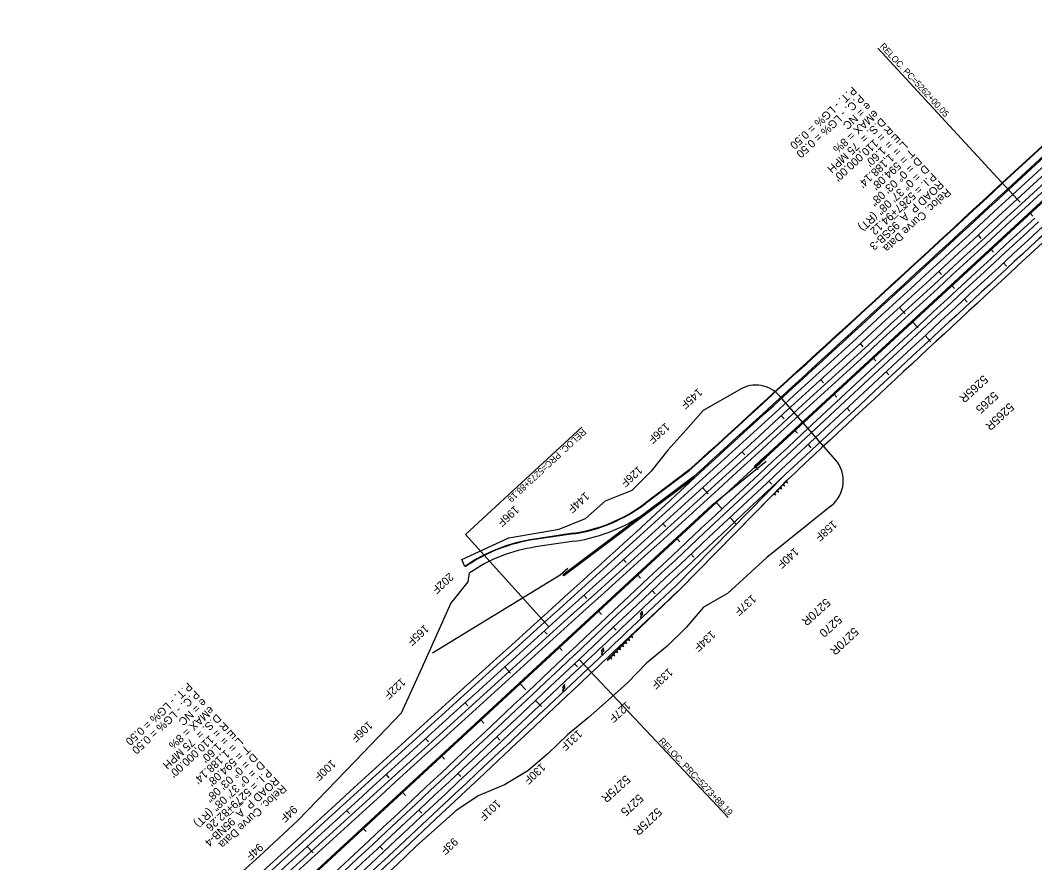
# Model space of a CAD drawing. Extents: x 2160876 to 2175625, y 601634 to 617693.
# Drawn here: x 2163705 to 2165605, y 606388 to 607966 of the extents above; entities that cross this region are included whole.
import ezdxf

# ---------------------------------------------------------------- set-up
doc = ezdxf.new("R2010")
doc.units = 0
for name, color, linetype in [('Level 20', 7, 'Continuous'), ('RD_HC_Cl', 7, 'Continuous'), ('RD_HC_CL_Rel', 7, 'Continuous'), ('RD_HC_Data_Rel', 7, 'Continuous'), ('RD_HC_Data_Tic', 7, 'Continuous'), ('RD_HC_Data_Tic_Rel', 7, 'Continuous'), ('RD_HC_TX_Rel_Sta50', 7, 'Continuous'), ('RD_HC_TX_Sta50', 7, 'Continuous'), ('RD_PD_CstnLmt', 7, 'Continuous'), ('RD_PD_Fence', 7, 'Continuous'), ('RD_PD_Final_LnLine', 7, 'Continuous'), ('RD_PD_Final_TrvlWay', 7, 'Continuous'), ('RD_PD_GR', 7, 'Continuous'), ('RD_PD_MedBWall', 7, 'Continuous'), ('RD_PD_MedGR', 7, 'Continuous')]:
    doc.layers.add(name, color=color, linetype=linetype)

msp = doc.modelspace()

# ---------------------------------------------------------------- linework, layer by layer
at = {"layer": 'Level 20'}
for points in [[(2164870.1, 606859), (2164866.1, 606853.3), (2164867.7, 606853.1)], [(2164867.7, 606853.1), (2164868, 606853.1), (2164866.4, 606847), (2164866.9, 606846.9)], [(2164866.9, 606846.9), (2164867.4, 606846.8), (2164869, 606852.8), (2164870.8, 606852), (2164870.1, 606859)], [(2164797.4, 606790.4), (2164793.3, 606784.7), (2164794.9, 606784.5)], [(2164794.9, 606784.5), (2164795.2, 606784.5), (2164793.6, 606778.4), (2164794.1, 606778.3)], [(2164794.1, 606778.3), (2164794.7, 606778.2), (2164796.3, 606784.2), (2164798, 606783.4), (2164797.4, 606790.4)], [(2164724.6, 606721.8), (2164720.6, 606716.1), (2164722.2, 606715.9)], [(2164722.2, 606715.9), (2164722.5, 606715.9), (2164720.8, 606709.8), (2164721.4, 606709.7)], [(2164721.4, 606709.7), (2164721.9, 606709.6), (2164723.5, 606715.6), (2164725.2, 606714.8), (2164724.6, 606721.8)]]:
    msp.add_lwpolyline(points, dxfattribs=at)
at = {"layer": 'RD_HC_Cl'}
msp.add_line((2172239.9, 613739.9), (2163704.8, 605858.6), dxfattribs=at)
at = {"layer": 'RD_HC_CL_Rel'}
msp.add_line((2168658.1, 610480.3), (2165572.4, 607631), dxfattribs=at)
for centre, start, end in [((2090947.4, 688446.2), 312.100607, 312.719474), ((2240245.2, 526764.1), 132.719474, 133.338341), ((2238443, 525213.1), 132.100607, 132.719474), ((2089258, 686773.1), 312.719474, 313.338341)]:
    msp.add_arc(centre, 110000, start, end, dxfattribs=at)
at = {"layer": 'RD_HC_Data_Rel'}
for p, q in [((2165572.4, 607631), (2165311.5, 607913.6)), ((2164538.9, 607002.7), (2164756.5, 607203.6)), ((2164695.2, 606829.7), (2164538.9, 607002.7)), ((2164751.6, 606768.6), (2165031.1, 606472.4))]:
    msp.add_line(p, q, dxfattribs=at)
at = {"layer": 'RD_HC_Data_Tic'}
for p, q in [((2165596.3, 607605.2), (2165601.7, 607599.3)), ((2165522.8, 607537.3), (2165528.2, 607531.4)), ((2165449.3, 607469.5), (2165454.8, 607463.6)), ((2165375.9, 607401.6), (2165386.7, 607389.9)), ((2165302.4, 607333.8), (2165307.8, 607327.9)), ((2165228.9, 607266), (2165234.4, 607260.1)), ((2165155.5, 607198.1), (2165160.9, 607192.2)), ((2165082, 607130.3), (2165087.4, 607124.4)), ((2165008.5, 607062.4), (2165019.4, 607050.7)), ((2164935.1, 606994.6), (2164940.5, 606988.7)), ((2164861.6, 606926.7), (2164867, 606920.9)), ((2164788.1, 606858.9), (2164793.6, 606853)), ((2164714.7, 606791.1), (2164720.1, 606785.2)), ((2164641.2, 606723.2), (2164652.1, 606711.5)), ((2164567.7, 606655.4), (2164573.2, 606649.5)), ((2164494.3, 606587.5), (2164499.7, 606581.7)), ((2164420.8, 606519.7), (2164426.2, 606513.8)), ((2164347.3, 606451.9), (2164352.8, 606446))]:
    msp.add_line(p, q, dxfattribs=at)
at = {"layer": 'RD_HC_Data_Tic_Rel'}
for p, q in [((2165572.5, 607631), (2165577.9, 607625.1)), ((2165499, 607563.2), (2165504.4, 607557.3)), ((2165546.7, 607511.5), (2165552.2, 607505.6)), ((2165425.4, 607495.5), (2165430.8, 607489.6)), ((2165473.4, 607443.5), (2165478.8, 607437.7)), ((2165351.8, 607427.8), (2165362.6, 607416)), ((2165400.1, 607375.5), (2165410.9, 607363.8)), ((2165278.1, 607360.2), (2165283.5, 607354.3)), ((2165326.8, 607307.5), (2165332.2, 607301.6)), ((2165204.4, 607292.7), (2165209.8, 607286.8)), ((2165130.5, 607225.2), (2165135.9, 607219.3)), ((2165253.6, 607239.3), (2165259.1, 607233.5)), ((2165180.5, 607171.1), (2165185.9, 607165.3)), ((2165056.7, 607157.8), (2165062.1, 607151.9)), ((2164982.7, 607090.4), (2164993.5, 607078.6)), ((2165107.4, 607102.8), (2165112.9, 607097)), ((2165034.4, 607034.5), (2165045.3, 607022.8)), ((2164908.8, 607023.2), (2164914.1, 607017.2)), ((2164834.7, 606956), (2164840.1, 606950)), ((2164961.5, 606966.1), (2164966.9, 606960.3)), ((2164888.6, 606897.6), (2164894.1, 606891.8)), ((2164760.6, 606888.8), (2164766, 606882.9)), ((2164686.4, 606821.8), (2164691.8, 606815.8)), ((2164815.8, 606829.1), (2164821.3, 606823.3)), ((2164612.3, 606754.7), (2164623, 606742.8)), ((2164743, 606760.5), (2164748.5, 606754.6)), ((2164670.2, 606691.9), (2164681.2, 606680.2)), ((2164538.2, 606687.5), (2164543.5, 606681.6)), ((2164464.1, 606620.3), (2164469.5, 606614.4)), ((2164597.4, 606623.4), (2164602.9, 606617.5)), ((2164390.2, 606553), (2164395.5, 606547.1)), ((2164524.5, 606554.9), (2164530, 606549.1)), ((2164316.2, 606485.7), (2164321.6, 606479.7)), ((2164451.6, 606486.5), (2164457, 606480.7)), ((2164242.4, 606418.2), (2164253.2, 606406.4)), ((2164378.5, 606418.2), (2164384, 606412.3))]:
    msp.add_line(p, q, dxfattribs=at)
at = {"layer": 'RD_PD_CstnLmt'}
for p, q in [((2164984.7, 607235.6), (2165052.8, 607274.5)), ((2165231.8, 607142.8), (2165127.7, 607261.9)), ((2164984.7, 607235.6), (2164951.5, 607197.9)), ((2164951.5, 607197.9), (2164918.1, 607160.4)), ((2164918.1, 607160.4), (2164886.4, 607121)), ((2165224.2, 607056.6), (2165103.5, 606959.6)), ((2165103.5, 606959.6), (2165029.4, 606892.4)), ((2165029.4, 606892.4), (2164985, 606866.8)), ((2164916.7, 606793.4), (2164878.1, 606761.5)), ((2164225.6, 606467.6), (2164152.6, 606399.2)), ((2164152.6, 606399.2), (2164077.9, 606332.8))]:
    msp.add_line(p, q, dxfattribs=at)
for points in [[(2164537.9, 606942.9), (2164531.9, 606955.8), (2164619.9, 606996.5), (2164714.3, 607012.5), (2164763.8, 607032.7), (2164801.3, 607065.7), (2164851.1, 607085.6), (2164886.4, 607121)], [(2164225.6, 606467.6), (2164332.1, 606578.3), (2164419, 606668.6), (2164457.4, 606753.8), (2164511.4, 606873.3), (2164543.9, 606914.3), (2164546.6, 606930.7)], [(2164985, 606866.8), (2164952.2, 606828.7), (2164916.7, 606793.4)], [(2164878.1, 606761.5), (2164843.2, 606725.6), (2164806, 606692.2), (2164768.4, 606659.1), (2164729.9, 606627.2), (2164693.8, 606592.6), (2164655.6, 606560.2), (2164612.2, 606533.5), (2164562.8, 606513.4), (2164521, 606484.9), (2164446.2, 606418.5), (2164410.1, 606383.9), (2164335.8, 606317), (2164259.9, 606251.7), (2164185.8, 606184.6), (2164112.5, 606116.5), (2164041.3, 606046.2), (2163998.3, 605983.1)]]:
    msp.add_lwpolyline(points, dxfattribs=at)
for centre, start, end in [((2165082.5, 607222.4), 41.1644, 119.7089), ((2165186.6, 607103.3), 308.7929, 41.1644)]:
    msp.add_arc(centre, 60, start, end, dxfattribs=at)
at = {"layer": 'RD_PD_Fence'}
msp.add_lwpolyline([(2164730.7, 606938.9), (2164716.2, 606926.5), (2164476.9, 606780.3)], dxfattribs=at)
at = {"layer": 'RD_PD_Final_LnLine'}
for p, q in [((2168630.1, 610510.7), (2165544.4, 607661.4)), ((2168630.7, 610509.9), (2165545.1, 607660.6)), ((2168650, 610489.1), (2165564.3, 607639.8)), ((2168658.1, 610480.3), (2165572.4, 607631)), ((2168666.2, 610471.5), (2165580.6, 607622.2)), ((2164957.1, 607123), (2164874.6, 607060.8)), ((2164957.8, 607122.2), (2164875.2, 607060)), ((2164932.9, 606906.3), (2165138.6, 607115.5)), ((2164740.7, 607004.9), (2164667.9, 606994.2)), ((2164740.9, 607003.9), (2164668.1, 606993.2)), ((2164742.7, 606990), (2164670.1, 606979.3))]:
    msp.add_line(p, q, dxfattribs=at)
for centre, radius, start, end in [((2090947.4, 688446.2), 109958.7, 312.303996, 312.719474), ((2090947.4, 688446.2), 109959.7, 312.303996, 312.719474), ((2090947.4, 688446.2), 109988, 312.100607, 312.719474), ((2090947.4, 688446.2), 110000, 312.100607, 312.719474), ((2090947.4, 688446.2), 110012, 312.100607, 312.719474), ((2240245.2, 526764.1), 110012, 132.719474, 133.338341), ((2240245.2, 526764.1), 110000, 132.719474, 133.338341), ((2240245.2, 526764.1), 109988, 132.719474, 133.067682), ((2240245.2, 526764.1), 109988, 133.067682, 133.220424), ((2164698.2, 607294.8), 293, 278.2992, 306.927), ((2164698.2, 607294.8), 294, 278.2992, 307.0089), ((2164698.2, 607294.8), 308, 278.2992, 307.0089), ((2164712.5, 606690.4), 307, 98.3571, 124.66), ((2164712.5, 606690.4), 306, 98.3571, 124.66), ((2164712.5, 606690.4), 292, 98.3571, 124.6285), ((2240245.2, 526764.1), 109988, 133.220424, 133.338341), ((2240245.2, 526764.1), 109976, 133.220424, 133.338341), ((2238443, 525213.1), 110012, 132.100607, 132.719474), ((2238443, 525213.1), 110000, 132.100607, 132.719474), ((2238443, 525213.1), 109988, 132.100607, 132.719474), ((2089258, 686773.1), 109988, 312.719474, 313.338341), ((2089258, 686773.1), 110000, 312.719474, 313.338341), ((2089258, 686773.1), 110012, 312.802799, 313.338341), ((2089258, 686773.1), 110024, 312.863734, 313.338341)]:
    msp.add_arc(centre, radius, start, end, dxfattribs=at)
at = {"layer": 'RD_PD_Final_TrvlWay'}
for p, q in [((2168641.8, 610497.9), (2165556.1, 607648.6)), ((2168673, 610464.1), (2165587.4, 607614.8)), ((2164968.2, 607109.7), (2164858.6, 607007.3)), ((2164939.7, 606899), (2165145.5, 607108.4))]:
    msp.add_line(p, q, dxfattribs=at)
for centre, radius, start, end in [((2090947.4, 688446.2), 109976, 312.30394, 312.719474), ((2090947.4, 688446.2), 110022, 312.100607, 312.719474), ((2240245.2, 526764.1), 110022, 132.719474, 133.338341), ((2240245.2, 526764.1), 109978, 132.719474, 133.067545), ((2090947.4, 688446.2), 109978, 312.100607, 312.2258), ((2240245.2, 526764.1), 109966, 133.220424, 133.338341), ((2238443, 525213.1), 110022, 132.100607, 132.719474), ((2238443, 525213.1), 109978, 132.100607, 132.719474), ((2089258, 686773.1), 109978, 312.719474, 313.338341), ((2089258, 686773.1), 110034, 312.803121, 313.338341)]:
    msp.add_arc(centre, radius, start, end, dxfattribs=at)
at = {"layer": 'RD_PD_GR'}
for p, q in [((2165000.3, 607057.6), (2165102, 607140.1)), ((2165141.1, 607104.2), (2165115.3, 607077.6)), ((2165115.7, 607077.3), (2165141.4, 607103.8)), ((2165127.9, 607089.8), (2165129.1, 607091.1)), ((2165129.3, 607088.4), (2165127.9, 607089.8)), ((2165129.1, 607091.1), (2165130.5, 607089.7)), ((2165130.5, 607089.7), (2165129.3, 607088.4)), ((2165129.9, 607089.1), (2165130.8, 607088.2)), ((2165130.2, 607087.6), (2165131.4, 607088.8)), ((2165133.4, 607095.6), (2165134.6, 607096.8)), ((2165134.9, 607094.2), (2165133.4, 607095.6)), ((2165134.6, 607096.8), (2165136.1, 607095.4)), ((2165136.1, 607095.4), (2165134.9, 607094.2)), ((2165135.5, 607094.8), (2165136.4, 607093.9)), ((2165135.8, 607093.3), (2165137, 607094.6)), ((2165139, 607101.3), (2165140.2, 607102.6)), ((2165140.4, 607099.9), (2165139, 607101.3)), ((2165140.2, 607102.6), (2165141.6, 607101.2)), ((2165141.6, 607101.2), (2165140.4, 607099.9)), ((2165141, 607100.6), (2165141.9, 607099.7)), ((2165141.4, 607103.8), (2165141.1, 607104.2)), ((2165141.3, 607099.1), (2165142.5, 607100.3)), ((2165115.3, 607077.6), (2165115.7, 607077.3)), ((2165116.7, 607078.4), (2165117.9, 607079.6)), ((2165118.1, 607077), (2165116.7, 607078.4)), ((2165117.9, 607079.6), (2165119.4, 607078.2)), ((2165119.4, 607078.2), (2165118.1, 607077)), ((2165118.8, 607077.6), (2165119.7, 607076.7)), ((2165119, 607076.1), (2165120.3, 607077.3)), ((2165120.1, 607081.9), (2165119.7, 607082.2)), ((2165122.3, 607084.1), (2165123.5, 607085.3)), ((2165123.7, 607082.7), (2165122.3, 607084.1)), ((2165123.5, 607085.3), (2165124.9, 607084)), ((2165124.9, 607084), (2165123.7, 607082.7)), ((2165124.3, 607083.3), (2165125.2, 607082.5)), ((2165124.6, 607081.8), (2165125.8, 607083.1)), ((2165000.3, 607057.6), (2163734.9, 605889.1)), ((2164849.7, 606813.1), (2164806.1, 606769)), ((2164807.1, 606769.3), (2164850, 606812.7)), ((2164843.2, 606805.8), (2164844.4, 606807)), ((2164844.6, 606804.4), (2164843.2, 606805.8)), ((2164844.4, 606807), (2164845.8, 606805.6)), ((2164845.8, 606805.6), (2164844.6, 606804.4)), ((2164845.2, 606805), (2164846.1, 606804.1)), ((2164845.5, 606803.5), (2164846.7, 606804.7)), ((2164848.8, 606811.5), (2164850, 606812.7)), ((2164850.2, 606810.1), (2164848.8, 606811.5)), ((2164850, 606812.7), (2164849.7, 606813.1)), ((2164850, 606812.7), (2164851.4, 606811.3)), ((2164851.4, 606811.3), (2164850.2, 606810.1)), ((2164850.8, 606810.7), (2164851.7, 606809.8)), ((2164851.1, 606809.2), (2164852.3, 606810.4)), ((2164815.4, 606783.7), (2164818, 606781)), ((2164820.7, 606783), (2164821.9, 606784.3)), ((2164821.9, 606784.3), (2164823.3, 606782.8)), ((2164826.3, 606788.7), (2164827.5, 606789.9)), ((2164827.7, 606787.3), (2164826.3, 606788.7)), ((2164827.5, 606789.9), (2164828.9, 606788.5)), ((2164828.9, 606788.5), (2164827.7, 606787.3)), ((2164828.3, 606787.9), (2164829.2, 606787)), ((2164828.6, 606786.4), (2164829.8, 606787.7)), ((2164831.9, 606794.4), (2164833.1, 606795.6)), ((2164833.3, 606793), (2164831.9, 606794.4)), ((2164833.1, 606795.6), (2164834.6, 606794.2)), ((2164834.6, 606794.2), (2164833.3, 606793)), ((2164834, 606793.6), (2164834.8, 606792.7)), ((2164834.2, 606792.1), (2164835.5, 606793.4)), ((2164837.5, 606800.1), (2164838.8, 606801.3)), ((2164839, 606798.7), (2164837.5, 606800.1)), ((2164838.8, 606801.3), (2164840.2, 606799.9)), ((2164840.2, 606799.9), (2164839, 606798.7)), ((2164839.6, 606799.3), (2164840.5, 606798.4)), ((2164839.8, 606797.8), (2164841.1, 606799)), ((2164806.1, 606769), (2164806.8, 606768.2)), ((2164806.6, 606769.1), (2164806.9, 606768.7)), ((2164806.8, 606768.2), (2164807.5, 606769)), ((2164807.5, 606769), (2164807.1, 606769.3)), ((2164809.4, 606771.6), (2164810.7, 606772.9)), ((2164810.9, 606770.2), (2164809.4, 606771.6)), ((2164810.7, 606772.9), (2164812.1, 606771.5)), ((2164812.1, 606771.5), (2164810.9, 606770.2)), ((2164811.5, 606770.8), (2164812.4, 606770)), ((2164811.7, 606769.3), (2164813, 606770.6)), ((2164815, 606777.3), (2164816.3, 606778.6)), ((2164816.5, 606775.9), (2164815, 606777.3)), ((2164816.3, 606778.6), (2164817.7, 606777.2)), ((2164817.7, 606777.2), (2164816.5, 606775.9)), ((2164817.1, 606776.5), (2164818, 606775.7)), ((2164817.4, 606775), (2164818.6, 606776.3)), ((2164822.1, 606781.6), (2164820.7, 606783)), ((2164823.3, 606782.8), (2164822.1, 606781.6)), ((2164822.7, 606782.2), (2164823.6, 606781.3)), ((2164823, 606780.7), (2164824.2, 606782))]:
    msp.add_line(p, q, dxfattribs=at)
for points in [[(2165115.3, 607077.6), (2164939.7, 606899), (2164849.6, 606813.1)], [(2164806.9, 606768.7), (2164806.4, 606766.8), (2164804.7, 606768.6), (2164806.6, 606769.1)]]:
    msp.add_lwpolyline(points, dxfattribs=at)
at = {"layer": 'RD_PD_MedBWall'}
for p, q in [((2168640.2, 610499.7), (2165554.6, 607650.3)), ((2168641.8, 610497.9), (2165556.1, 607648.6)), ((2168454, 610245.6), (2165100.2, 607148.7)), ((2168455.6, 610243.9), (2165101.8, 607146.9)), ((2165101.8, 607146.9), (2165100.2, 607148.7)), ((2164966.7, 607111.5), (2164721.8, 606926.8)), ((2164968.2, 607109.7), (2164723.2, 606925)), ((2164723.2, 606925), (2164721.8, 606926.8))]:
    msp.add_line(p, q, dxfattribs=at)
for radius, start in [(109973.7, 312.303996), (109976, 312.30394)]:
    msp.add_arc((2090947.4, 688446.2), radius, start, 312.719474, dxfattribs=at)
at = {"layer": 'RD_PD_MedGR'}
for p, q in [((2165099.9, 607149), (2165080, 607130.7)), ((2165099.9, 607149), (2165080, 607130.7)), ((2165097.3, 607145.9), (2165080.4, 607130.3)), ((2165102.1, 607146.6), (2165082.3, 607128.3)), ((2165082.3, 607128.3), (2165102.1, 607146.6)), ((2165095.5, 607144.3), (2165095.8, 607144.6)), ((2165095.8, 607144.6), (2165097.3, 607145.9)), ((2165097.4, 607142.9), (2165095.8, 607144.6)), ((2165100.2, 607148.7), (2165097.3, 607145.9)), ((2165097.3, 607145.9), (2165100.2, 607148.7)), ((2165098.8, 607144.2), (2165097.3, 607145.9)), ((2165101.8, 607146.9), (2165098.8, 607144.2)), ((2165101.8, 607146.9), (2165098.8, 607144.2)), ((2165099.9, 607149), (2165100.2, 607148.7)), ((2165100.2, 607148.7), (2165099.9, 607149)), ((2165102.1, 607146.6), (2165101.8, 607146.9)), ((2165102.1, 607146.6), (2165101.8, 607146.9)), ((2165082.3, 607128.3), (2165080, 607130.7)), ((2165080.3, 607130.4), (2165080, 607130.7)), ((2165098.8, 607144.2), (2165081.9, 607128.6)), ((2165082.3, 607128.3), (2165082, 607128.6)), ((2165083.9, 607130.4), (2165082.3, 607132.1)), ((2165082.6, 607132.4), (2165084.5, 607134.1)), ((2165084.1, 607130.7), (2165082.6, 607132.4)), ((2165084.5, 607134.1), (2165084.8, 607134.4)), ((2165086.1, 607132.4), (2165084.5, 607134.1)), ((2165084.8, 607134.4), (2165086.7, 607136.2)), ((2165086.4, 607132.7), (2165084.8, 607134.4)), ((2165086.7, 607136.2), (2165087, 607136.4)), ((2165088.3, 607134.5), (2165086.7, 607136.2)), ((2165087, 607136.4), (2165088.9, 607138.2)), ((2165088.6, 607134.7), (2165087, 607136.4)), ((2165088.9, 607138.2), (2165089.2, 607138.5)), ((2165090.5, 607136.5), (2165088.9, 607138.2)), ((2165089.2, 607138.5), (2165091.1, 607140.2)), ((2165090.8, 607136.8), (2165089.2, 607138.5)), ((2165091.1, 607140.2), (2165091.4, 607140.5)), ((2165092.7, 607138.5), (2165091.1, 607140.2)), ((2165091.4, 607140.5), (2165093.3, 607142.3)), ((2165093, 607138.8), (2165091.4, 607140.5)), ((2165093.3, 607142.3), (2165093.6, 607142.5)), ((2165094.9, 607140.6), (2165093.3, 607142.3)), ((2165093.6, 607142.5), (2165095.5, 607144.3)), ((2165095.2, 607140.8), (2165093.6, 607142.5)), ((2165097.1, 607142.6), (2165095.5, 607144.3))]:
    msp.add_line(p, q, dxfattribs=at)
for points in [[(2165080, 607130.7), (2165080.3, 607130.4), (2165080.4, 607130.3)], [(2165080.4, 607130.3), (2165082.3, 607132.1), (2165082.6, 607132.4)], [(2165098.8, 607144.2), (2165097.4, 607142.9), (2165097.1, 607142.6), (2165095.2, 607140.8), (2165094.9, 607140.6), (2165093, 607138.8), (2165092.7, 607138.5), (2165090.8, 607136.8), (2165090.5, 607136.5), (2165088.6, 607134.7), (2165088.3, 607134.5), (2165086.4, 607132.7), (2165086.1, 607132.4), (2165084.1, 607130.7), (2165083.9, 607130.4), (2165081.9, 607128.6)], [(2165081.9, 607128.6), (2165082, 607128.6), (2165082.3, 607128.3)]]:
    msp.add_lwpolyline(points, dxfattribs=at)
for radius in [1.67, 1.67, 1.27, 1.27]:
    msp.add_arc((2165081.2, 607129.5), radius, 132.7195, 312.7195, dxfattribs=at)

# ---------------------------------------------------------------- texts
at = {"layer": 'RD_HC_Data_Rel'}
for s, height, rotation, p in [('RELOC. PC=5262+00.05', 12, 312.7195, (2165314.2, 607916.6)), ('P.T. - LG% = 0.50', 15, 222.7195, (2165263.7, 607843.1)), ('P.C. - LG% = 0.50', 15, 222.7195, (2165277.3, 607828.4)), ('e = NC', 15, 222.7195, (2165290.8, 607813.7)), ('eMAX = 8%', 15, 222.7195, (2165304.4, 607799)), ('D.S. =  75 MPH', 15, 222.7195, (2165318, 607784.3)), ("R = 110,000.00'", 15, 222.7195, (2165331.5, 607769.6)), ("E = 1.60'", 15, 222.7195, (2165345.1, 607754.9)), ("L = 1,188.14'", 15, 222.7195, (2165358.7, 607740.3)), ("T = 594.08'", 15, 222.7195, (2165372.2, 607725.6)), ('D = 0° 03\' 08"', 15, 222.7195, (2165385.8, 607710.9)), ('    = 0° 37\' 08" (RT)', 15, 222.7195, (2165399.4, 607696.2)), ('P.I. = 5267+94.12', 15, 222.7195, (2165412.9, 607681.5)), ('D', 15, 222.7195, (2165399.4, 607696.2)), ('ROAD P_A_95SB-3', 15, 222.7195, (2165426.5, 607666.8)), ('Reloc. Curve Data', 15, 222.7195, (2165440.1, 607652.1)), ('RELOC. PRC=5273+88.19', 12, 222.7195, (2164758.3, 607201.7)), ('P.T. - LG% = 0.50', 15, 222.7195, (2164019, 606726.3)), ('P.C. - LG% = 0.50', 15, 222.7195, (2164032.5, 606711.6)), ('e = NC', 15, 222.7195, (2164046.1, 606696.9)), ('eMAX = 8%', 15, 222.7195, (2164059.7, 606682.2)), ('D.S. =  75 MPH', 15, 222.7195, (2164073.2, 606667.5)), ("R = 110,000.00'", 15, 222.7195, (2164086.8, 606652.8)), ("E = 1.60'", 15, 222.7195, (2164100.4, 606638.1)), ("L = 1,188.14'", 15, 222.7195, (2164113.9, 606623.4)), ('RELOC. PRC=5273+88.19', 12, 313.3383, (2164899.9, 606615.2)), ("T = 594.08'", 15, 222.7195, (2164127.5, 606608.7)), ('D = 0° 03\' 08"', 15, 222.7195, (2164141.1, 606594)), ('D', 15, 222.7195, (2164154.6, 606579.3)), ('    = 0° 37\' 08" (RT)', 15, 222.7195, (2164154.6, 606579.3)), ('P.I. = 5279+82.26', 15, 222.7195, (2164168.2, 606564.6)), ('ROAD P_A_95NB-4', 15, 222.7195, (2164181.8, 606550)), ('Reloc. Curve Data', 15, 222.7195, (2164195.4, 606535.3))]:
    msp.add_text(s, height=height, rotation=rotation, dxfattribs=at).set_placement(p)
at = {"layer": 'RD_HC_TX_Rel_Sta50'}
for s, rotation, p in [('5265R', 222.5632, (2165509, 607302.4)), ('5265R', 222.8757, (2165557.6, 607250.6)), ('5270R', 222.3028, (2165213.8, 606884.3)), ('5270R', 223.1361, (2165266.4, 606829.8)), ('5275R', 222.1588, (2164838.9, 606553)), ('5275R', 223.2801, (2164898, 606492.1))]:
    msp.add_text(s, height=16, rotation=rotation, dxfattribs=at).set_placement(p)
at = {"layer": 'RD_HC_TX_Sta50'}
for s, p in [('5265', (2165528.1, 607271.7)), ('5270', (2165235.2, 606852.5)), ('5275', (2164863.2, 606517.7))]:
    msp.add_text(s, height=16, rotation=222.7195, dxfattribs=at).set_placement(p)
at = {"layer": 'RD_PD_CstnLmt'}
for s, rotation, p in [('145F', 221.3554, (2164974.8, 607277.7)), ('136F', 221.5463, (2164913.6, 607213)), ('126F', 221.7373, (2164862.6, 607131.9)), ('144F', 221.9283, (2164762.9, 607083.1)), ('196F', 222.1193, (2164631.2, 607057.8)), ('158F', 221.3554, (2165226.9, 607030.1)), ('140F', 221.5463, (2165155.4, 606979.1)), ('202F', 222.5013, (2164508.5, 606932)), ('137F', 221.7373, (2165075.4, 606890.9)), ('165F', 222.5234, (2164462.1, 606834.8)), ('134F', 221.9283, (2164999.1, 606823.6)), ('133F', 222.1193, (2164919.3, 606753.4)), ('122F', 222.5234, (2164418.5, 606734.6)), ('127F', 222.3103, (2164840, 606690.8)), ('106F', 222.5234, (2164356.8, 606654.1)), ('131F', 222.5013, (2164749.5, 606638)), ('100F', 222.5234, (2164287.8, 606581.7)), ('130F', 222.5234, (2164680.7, 606575.3)), ('101F', 222.5234, (2164597, 606507.1)), ('94F', 222.5234, (2164215.7, 606496.4)), ('94F', 222.5234, (2164151.6, 606425.5)), ('93F', 222.5234, (2164516.5, 606435.8))]:
    msp.add_text(s, height=15, rotation=rotation, dxfattribs=at).set_placement(p)

doc.saveas('drawing.dxf')
